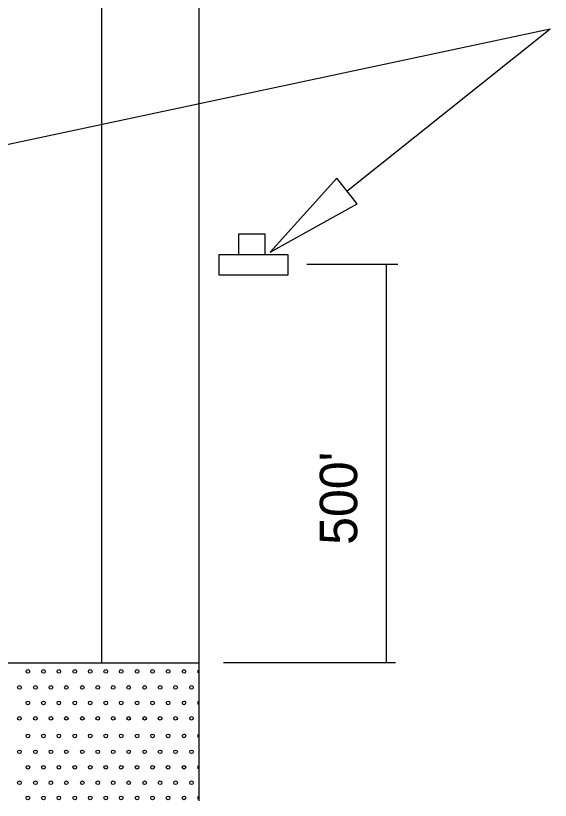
# Model space of a CAD drawing. Extents: x 1536.8 to 1543.6, y 1529.9 to 1539.9.
# Drawn here: x 1540.276 to 1541.133, y 1537.848 to 1539.106 of the extents above; entities that cross this region are included whole.
import ezdxf

# ---------------------------------------------------------------- set-up
doc = ezdxf.new("R2010")
doc.units = 0
for name, color, linetype in [('DETL-DIMS', 7, 'Continuous'), ('DETL-LINE', 7, 'Continuous'), ('DETL-NOTE', 7, 'Continuous'), ('USER-BORD', 7, 'Continuous')]:
    doc.layers.add(name, color=color, linetype=linetype)

# ---------------------------------------------------------------- blocks, each defined once
blk = doc.blocks.new('SIGN13')
at = {"layer": 'USER-BORD'}
for points in [[(-0.0134, 0.0182), (0.011, 0.0189), (0.011, 0.0371), (-0.0134, 0.0371)], [(-0.0314, 0.0182), (-0.0314, 0), (0.032, 0), (0.032, 0.0182)]]:
    blk.add_lwpolyline(points, close=True, dxfattribs=at)

msp = doc.modelspace()

# ---------------------------------------------------------------- linework, layer by layer
at = {"layer": 'DETL-DIMS'}
for p, q in [((1539.6501, 1538.7696), (1541.1332, 1539.0852)), ((1540.8071, 1538.8251), (1541.1332, 1539.0852)), ((1540.7426, 1538.7078), (1540.8888, 1538.7078)), ((1540.8701, 1538.7078), (1540.8701, 1538.0692)), ((1540.6087, 1538.0692), (1540.8848, 1538.0692))]:
    msp.add_line(p, q, dxfattribs=at)
msp.add_lwpolyline([(1540.8235, 1538.8046), (1540.7908, 1538.8456), (1540.684, 1538.7268)], close=True, dxfattribs=at)
at = {"layer": 'DETL-LINE'}
for p, q in [((1540.4133, 1539.3785), (1540.4133, 1538.068)), ((1540.5695, 1539.3785), (1540.5695, 1538.068)), ((1540.5695, 1538.068), (1539.6016, 1538.068)), ((1540.5695, 1538.068), (1540.5695, 1537.8471)), ((1540.2943, 1538.0548), (1540.2943, 1538.0548)), ((1540.2951, 1538.0548), (1540.2951, 1538.0548)), ((1540.3191, 1538.0548), (1540.3191, 1538.0548)), ((1540.3199, 1538.0548), (1540.3199, 1538.0548)), ((1540.3447, 1538.0548), (1540.3447, 1538.0548)), ((1540.3447, 1538.0548), (1540.3447, 1538.0548)), ((1540.3695, 1538.0548), (1540.3695, 1538.0548)), ((1540.3703, 1538.0548), (1540.3703, 1538.0548)), ((1540.3943, 1538.0548), (1540.3943, 1538.0548)), ((1540.3951, 1538.0548), (1540.3951, 1538.0548)), ((1540.4191, 1538.0548), (1540.4191, 1538.0548)), ((1540.4199, 1538.0548), (1540.4199, 1538.0548)), ((1540.4447, 1538.0548), (1540.4447, 1538.0548)), ((1540.4447, 1538.0548), (1540.4447, 1538.0548)), ((1540.4695, 1538.0548), (1540.4695, 1538.0548)), ((1540.4703, 1538.0548), (1540.4703, 1538.0548)), ((1540.4943, 1538.0548), (1540.4943, 1538.0548)), ((1540.4951, 1538.0548), (1540.4951, 1538.0548)), ((1540.5199, 1538.0548), (1540.5199, 1538.0548)), ((1540.5199, 1538.0548), (1540.5199, 1538.0548)), ((1540.5447, 1538.0548), (1540.5447, 1538.0548)), ((1540.5455, 1538.0548), (1540.5455, 1538.0548)), ((1540.2815, 1538.0292), (1540.2815, 1538.0292)), ((1540.3071, 1538.0292), (1540.3071, 1538.0292)), ((1540.3319, 1538.0292), (1540.3319, 1538.0292)), ((1540.3567, 1538.0292), (1540.3567, 1538.0292)), ((1540.3823, 1538.0292), (1540.3823, 1538.0292)), ((1540.4071, 1538.0292), (1540.4071, 1538.0292)), ((1540.4319, 1538.0292), (1540.4319, 1538.0292)), ((1540.4567, 1538.0292), (1540.4567, 1538.0292)), ((1540.4823, 1538.0292), (1540.4823, 1538.0292)), ((1540.5071, 1538.0292), (1540.5071, 1538.0292)), ((1540.5319, 1538.0292), (1540.5319, 1538.0292)), ((1540.5575, 1538.0292), (1540.5575, 1538.0292)), ((1540.2943, 1538.0044), (1540.2943, 1538.0044)), ((1540.2951, 1538.0044), (1540.2951, 1538.0044)), ((1540.3191, 1538.0044), (1540.3191, 1538.0044)), ((1540.3199, 1538.0044), (1540.3199, 1538.0044)), ((1540.3447, 1538.0044), (1540.3447, 1538.0044)), ((1540.3447, 1538.0044), (1540.3447, 1538.0044)), ((1540.3695, 1538.0044), (1540.3695, 1538.0044)), ((1540.3703, 1538.0044), (1540.3703, 1538.0044)), ((1540.3943, 1538.0044), (1540.3943, 1538.0044)), ((1540.3951, 1538.0044), (1540.3951, 1538.0044)), ((1540.4191, 1538.0044), (1540.4191, 1538.0044)), ((1540.4199, 1538.0044), (1540.4199, 1538.0044)), ((1540.4447, 1538.0044), (1540.4447, 1538.0044)), ((1540.4447, 1538.0044), (1540.4447, 1538.0044)), ((1540.4695, 1538.0044), (1540.4695, 1538.0044)), ((1540.4703, 1538.0044), (1540.4703, 1538.0044)), ((1540.4943, 1538.0044), (1540.4943, 1538.0044)), ((1540.4951, 1538.0044), (1540.4951, 1538.0044)), ((1540.5199, 1538.0044), (1540.5199, 1538.0044)), ((1540.5199, 1538.0044), (1540.5199, 1538.0044)), ((1540.5447, 1538.0044), (1540.5447, 1538.0044)), ((1540.5455, 1538.0044), (1540.5455, 1538.0044)), ((1540.2815, 1537.9796), (1540.2815, 1537.9796)), ((1540.2815, 1537.9796), (1540.2815, 1537.9796)), ((1540.3071, 1537.9796), (1540.3071, 1537.9796)), ((1540.3071, 1537.9796), (1540.3071, 1537.9796)), ((1540.3319, 1537.9796), (1540.3319, 1537.9796)), ((1540.3319, 1537.9796), (1540.3319, 1537.9796)), ((1540.3567, 1537.9796), (1540.3567, 1537.9796)), ((1540.3567, 1537.9796), (1540.3567, 1537.9796)), ((1540.3823, 1537.9796), (1540.3823, 1537.9796)), ((1540.3823, 1537.9796), (1540.3823, 1537.9796)), ((1540.4071, 1537.9796), (1540.4071, 1537.9796)), ((1540.4071, 1537.9796), (1540.4071, 1537.9796)), ((1540.4319, 1537.9796), (1540.4319, 1537.9796)), ((1540.4319, 1537.9796), (1540.4319, 1537.9796)), ((1540.4567, 1537.9796), (1540.4567, 1537.9796)), ((1540.4567, 1537.9796), (1540.4567, 1537.9796)), ((1540.4823, 1537.9796), (1540.4823, 1537.9796)), ((1540.4823, 1537.9796), (1540.4823, 1537.9796)), ((1540.5071, 1537.9796), (1540.5071, 1537.9796)), ((1540.5071, 1537.9796), (1540.5071, 1537.9796)), ((1540.5319, 1537.9796), (1540.5319, 1537.9796)), ((1540.5319, 1537.9796), (1540.5319, 1537.9796)), ((1540.5575, 1537.9796), (1540.5575, 1537.9796)), ((1540.5575, 1537.9796), (1540.5575, 1537.9796)), ((1540.2943, 1537.9516), (1540.2943, 1537.9516)), ((1540.2951, 1537.9516), (1540.2951, 1537.9516)), ((1540.3191, 1537.9516), (1540.3191, 1537.9516)), ((1540.3199, 1537.9516), (1540.3199, 1537.9516)), ((1540.3447, 1537.9516), (1540.3447, 1537.9516)), ((1540.3447, 1537.9516), (1540.3447, 1537.9516)), ((1540.3695, 1537.9516), (1540.3695, 1537.9516)), ((1540.3703, 1537.9516), (1540.3703, 1537.9516)), ((1540.3943, 1537.9516), (1540.3943, 1537.9516)), ((1540.3951, 1537.9516), (1540.3951, 1537.9516)), ((1540.4191, 1537.9516), (1540.4191, 1537.9516)), ((1540.4199, 1537.9516), (1540.4199, 1537.9516)), ((1540.4447, 1537.9516), (1540.4447, 1537.9516)), ((1540.4447, 1537.9516), (1540.4447, 1537.9516)), ((1540.4695, 1537.9516), (1540.4695, 1537.9516)), ((1540.4703, 1537.9516), (1540.4703, 1537.9516)), ((1540.4943, 1537.9516), (1540.4943, 1537.9516)), ((1540.4951, 1537.9516), (1540.4951, 1537.9516)), ((1540.5199, 1537.9516), (1540.5199, 1537.9516)), ((1540.5199, 1537.9516), (1540.5199, 1537.9516)), ((1540.5447, 1537.9516), (1540.5447, 1537.9516)), ((1540.5455, 1537.9516), (1540.5455, 1537.9516)), ((1540.2815, 1537.926), (1540.2815, 1537.926)), ((1540.3071, 1537.926), (1540.3071, 1537.926)), ((1540.3319, 1537.926), (1540.3319, 1537.926)), ((1540.3567, 1537.926), (1540.3567, 1537.926)), ((1540.3823, 1537.926), (1540.3823, 1537.926)), ((1540.4071, 1537.926), (1540.4071, 1537.926)), ((1540.4319, 1537.926), (1540.4319, 1537.926)), ((1540.4567, 1537.926), (1540.4567, 1537.926)), ((1540.4823, 1537.926), (1540.4823, 1537.926)), ((1540.5071, 1537.926), (1540.5071, 1537.926)), ((1540.5319, 1537.926), (1540.5319, 1537.926)), ((1540.5575, 1537.926), (1540.5575, 1537.926)), ((1540.2943, 1537.9012), (1540.2943, 1537.9012)), ((1540.2951, 1537.9012), (1540.2951, 1537.9012)), ((1540.3191, 1537.9012), (1540.3191, 1537.9012)), ((1540.3199, 1537.9012), (1540.3199, 1537.9012)), ((1540.3447, 1537.9012), (1540.3447, 1537.9012)), ((1540.3447, 1537.9012), (1540.3447, 1537.9012)), ((1540.3695, 1537.9012), (1540.3695, 1537.9012)), ((1540.3703, 1537.9012), (1540.3703, 1537.9012)), ((1540.3943, 1537.9012), (1540.3943, 1537.9012)), ((1540.3951, 1537.9012), (1540.3951, 1537.9012)), ((1540.4191, 1537.9012), (1540.4191, 1537.9012)), ((1540.4199, 1537.9012), (1540.4199, 1537.9012)), ((1540.4447, 1537.9012), (1540.4447, 1537.9012)), ((1540.4447, 1537.9012), (1540.4447, 1537.9012)), ((1540.4695, 1537.9012), (1540.4695, 1537.9012)), ((1540.4703, 1537.9012), (1540.4703, 1537.9012)), ((1540.4943, 1537.9012), (1540.4943, 1537.9012)), ((1540.4951, 1537.9012), (1540.4951, 1537.9012)), ((1540.5199, 1537.9012), (1540.5199, 1537.9012)), ((1540.5199, 1537.9012), (1540.5199, 1537.9012)), ((1540.5447, 1537.9012), (1540.5447, 1537.9012)), ((1540.5455, 1537.9012), (1540.5455, 1537.9012)), ((1540.2815, 1537.8764), (1540.2815, 1537.8764)), ((1540.2815, 1537.8764), (1540.2815, 1537.8764)), ((1540.3071, 1537.8764), (1540.3071, 1537.8764)), ((1540.3071, 1537.8764), (1540.3071, 1537.8764)), ((1540.3319, 1537.8764), (1540.3319, 1537.8764)), ((1540.3319, 1537.8764), (1540.3319, 1537.8764)), ((1540.3567, 1537.8764), (1540.3567, 1537.8764)), ((1540.3567, 1537.8764), (1540.3567, 1537.8764)), ((1540.3823, 1537.8764), (1540.3823, 1537.8764)), ((1540.3823, 1537.8764), (1540.3823, 1537.8764)), ((1540.4071, 1537.8764), (1540.4071, 1537.8764)), ((1540.4071, 1537.8764), (1540.4071, 1537.8764)), ((1540.4319, 1537.8764), (1540.4319, 1537.8764)), ((1540.4319, 1537.8764), (1540.4319, 1537.8764)), ((1540.4567, 1537.8764), (1540.4567, 1537.8764)), ((1540.4567, 1537.8764), (1540.4567, 1537.8764)), ((1540.4823, 1537.8764), (1540.4823, 1537.8764)), ((1540.4823, 1537.8764), (1540.4823, 1537.8764)), ((1540.5071, 1537.8764), (1540.5071, 1537.8764)), ((1540.5071, 1537.8764), (1540.5071, 1537.8764)), ((1540.5319, 1537.8764), (1540.5319, 1537.8764)), ((1540.5319, 1537.8764), (1540.5319, 1537.8764)), ((1540.5575, 1537.8764), (1540.5575, 1537.8764)), ((1540.5575, 1537.8764), (1540.5575, 1537.8764)), ((1540.2943, 1537.8521), (1540.2943, 1537.8521)), ((1540.2951, 1537.8521), (1540.2951, 1537.8521)), ((1540.3191, 1537.8521), (1540.3191, 1537.8521)), ((1540.3199, 1537.8521), (1540.3199, 1537.8521)), ((1540.3447, 1537.8521), (1540.3447, 1537.8521)), ((1540.3447, 1537.8521), (1540.3447, 1537.8521)), ((1540.3695, 1537.8521), (1540.3695, 1537.8521)), ((1540.3703, 1537.8521), (1540.3703, 1537.8521)), ((1540.3943, 1537.8521), (1540.3943, 1537.8521)), ((1540.3951, 1537.8521), (1540.3951, 1537.8521)), ((1540.4191, 1537.8521), (1540.4191, 1537.8521)), ((1540.4199, 1537.8521), (1540.4199, 1537.8521)), ((1540.4447, 1537.8521), (1540.4447, 1537.8521)), ((1540.4447, 1537.8521), (1540.4447, 1537.8521)), ((1540.4695, 1537.8521), (1540.4695, 1537.8521)), ((1540.4703, 1537.8521), (1540.4703, 1537.8521)), ((1540.4943, 1537.8521), (1540.4943, 1537.8521)), ((1540.4951, 1537.8521), (1540.4951, 1537.8521)), ((1540.5199, 1537.8521), (1540.5199, 1537.8521)), ((1540.5199, 1537.8521), (1540.5199, 1537.8521)), ((1540.5447, 1537.8521), (1540.5447, 1537.8521)), ((1540.5455, 1537.8521), (1540.5455, 1537.8521))]:
    msp.add_line(p, q, dxfattribs=at)
for points in [[(1540.5684, 1538.0525), (1540.5684, 1538.0569)], [(1540.5684, 1538.0021), (1540.5684, 1538.0065)], [(1540.5684, 1537.9492), (1540.5684, 1537.9536)], [(1540.5684, 1537.8988), (1540.5684, 1537.9032)], [(1540.5684, 1537.8498), (1540.5684, 1537.8541)]]:
    msp.add_lwpolyline(points, dxfattribs=at)
for centre in [(1540.2952, 1538.0547), (1540.32, 1538.0547), (1540.3448, 1538.0547), (1540.3704, 1538.0547), (1540.3952, 1538.0547), (1540.42, 1538.0547), (1540.4448, 1538.0547), (1540.4704, 1538.0547), (1540.4952, 1538.0547), (1540.52, 1538.0547), (1540.5456, 1538.0547), (1540.2816, 1538.0291), (1540.3072, 1538.0291), (1540.332, 1538.0291), (1540.3568, 1538.0291), (1540.3824, 1538.0291), (1540.4072, 1538.0291), (1540.432, 1538.0291), (1540.4568, 1538.0291), (1540.4824, 1538.0291), (1540.5072, 1538.0291), (1540.532, 1538.0291), (1540.5576, 1538.0291), (1540.2952, 1538.0043), (1540.32, 1538.0043), (1540.3448, 1538.0043), (1540.3704, 1538.0043), (1540.3952, 1538.0043), (1540.42, 1538.0043), (1540.4448, 1538.0043), (1540.4704, 1538.0043), (1540.4952, 1538.0043), (1540.52, 1538.0043), (1540.5456, 1538.0043), (1540.2816, 1537.9795), (1540.3072, 1537.9795), (1540.332, 1537.9795), (1540.3568, 1537.9795), (1540.3824, 1537.9795), (1540.4072, 1537.9795), (1540.432, 1537.9795), (1540.4568, 1537.9795), (1540.4824, 1537.9795), (1540.5072, 1537.9795), (1540.532, 1537.9795), (1540.5576, 1537.9795), (1540.2952, 1537.9514), (1540.32, 1537.9514), (1540.3448, 1537.9514), (1540.3704, 1537.9514), (1540.3952, 1537.9514), (1540.42, 1537.9514), (1540.4448, 1537.9514), (1540.4704, 1537.9514), (1540.4952, 1537.9514), (1540.52, 1537.9514), (1540.5456, 1537.9514), (1540.2816, 1537.9258), (1540.3072, 1537.9258), (1540.332, 1537.9258), (1540.3568, 1537.9258), (1540.3824, 1537.9258), (1540.4072, 1537.9258), (1540.432, 1537.9258), (1540.4568, 1537.9258), (1540.4824, 1537.9258), (1540.5072, 1537.9258), (1540.532, 1537.9258), (1540.5576, 1537.9258), (1540.2952, 1537.901), (1540.32, 1537.901), (1540.3448, 1537.901), (1540.3704, 1537.901), (1540.3952, 1537.901), (1540.42, 1537.901), (1540.4448, 1537.901), (1540.4704, 1537.901), (1540.4952, 1537.901), (1540.52, 1537.901), (1540.5456, 1537.901), (1540.2816, 1537.8762), (1540.3072, 1537.8762), (1540.332, 1537.8762), (1540.3568, 1537.8762), (1540.3824, 1537.8762), (1540.4072, 1537.8762), (1540.432, 1537.8762), (1540.4568, 1537.8762), (1540.4824, 1537.8762), (1540.5072, 1537.8762), (1540.532, 1537.8762), (1540.5576, 1537.8762), (1540.2952, 1537.8519), (1540.32, 1537.8519), (1540.3448, 1537.8519), (1540.3704, 1537.8519), (1540.3952, 1537.8519), (1540.42, 1537.8519), (1540.4448, 1537.8519), (1540.4704, 1537.8519), (1540.4952, 1537.8519), (1540.52, 1537.8519), (1540.5456, 1537.8519)]:
    msp.add_circle(centre, 0.00291, dxfattribs=at)
for centre in [(1540.5704, 1538.0547), (1540.5704, 1538.0043), (1540.5704, 1537.9514), (1540.5704, 1537.901), (1540.5704, 1537.8519)]:
    msp.add_arc(centre, 0.00291, 130.9943, 229.0057, dxfattribs=at)

# ---------------------------------------------------------------- block references
at = {"layer": 'DETL-LINE', "xscale": 1.7510019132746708, "yscale": 1.751001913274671}
msp.add_blockref('SIGN13', (1540.6564, 1538.6908), dxfattribs=at)

# ---------------------------------------------------------------- texts
at = {"layer": 'DETL-NOTE'}
msp.add_text("500'", height=0.06, rotation=90, dxfattribs=at).set_placement((1540.8234, 1538.2577))

doc.saveas('drawing.dxf')
